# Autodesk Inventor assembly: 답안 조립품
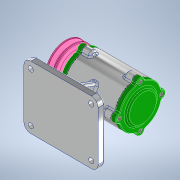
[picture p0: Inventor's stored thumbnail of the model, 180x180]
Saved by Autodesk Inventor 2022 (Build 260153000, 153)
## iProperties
Created: 2023-05
Part Number: 답안 조립품
Document SubType Name: Assembly
Designer: Admin
Author: Admin
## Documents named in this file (12)
- C:\Users\Admin\Desktop\730508V1004\답안 조립품.iam
- C:\Users\Admin\Desktop\730508V1004\본체.ipt
- C:\Users\Admin\Desktop\730508V1004\개스킷.ipt
- C:\Users\Admin\Desktop\730508V1004\앞커버.ipt
- C:\Users\Admin\Desktop\730508V1004\뒤커버.ipt
- C:\Users\Admin\Desktop\730508V1004\베어링 6204.ipt
- C:\Users\Admin\Desktop\730508V1004\오일 실.ipt
- C:\Users\Admin\Desktop\730508V1004\축.ipt
- C:\Users\Admin\Desktop\730508V1004\볼트 M4 x 12.ipt
- C:\Users\Admin\Desktop\730508V1004\키 4 x 4.ipt
- C:\Users\Admin\Desktop\730508V1004\V-벨트풀리.ipt
- C:\Users\Admin\Desktop\730508V1004\너트 M12 x 1.25.ipt
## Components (8 placed, 6 different names)
1. 개스킷:1
2. 개스킷:2
3. KS B 2023 6204 - 20 x 47 x 14:1
4. KS B 2023 6204 - 20 x 47 x 14:2
5. KS B 2804 D D - 20 32 8:1
6. KS B 1311 (I) 4 x 4 x 12:1
7. V-벨트풀리:1
8. KS B 1012 클래스 1 일반 - 미터 M12x1.25:1
